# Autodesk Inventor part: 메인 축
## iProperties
Created: 2014-07
Part Number: 메인 축
Material: Steel
Document SubType Name: Modeling
Designer: KYOUNG IL JANG
Categories: <?xml version="1.0" encoding="UTF-16"?> <MemberInstance><Categories><FamilyTemplate><FamilyTemplateParameter ValueType="xs:double" Id="1" ObjectReferenceKey="da
Density: 1 g/cm^3
CustomPartVersion: 1
Company: 한국ATC센터
Author: KYOUNG IL JANG
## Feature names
1. Extrusion1
